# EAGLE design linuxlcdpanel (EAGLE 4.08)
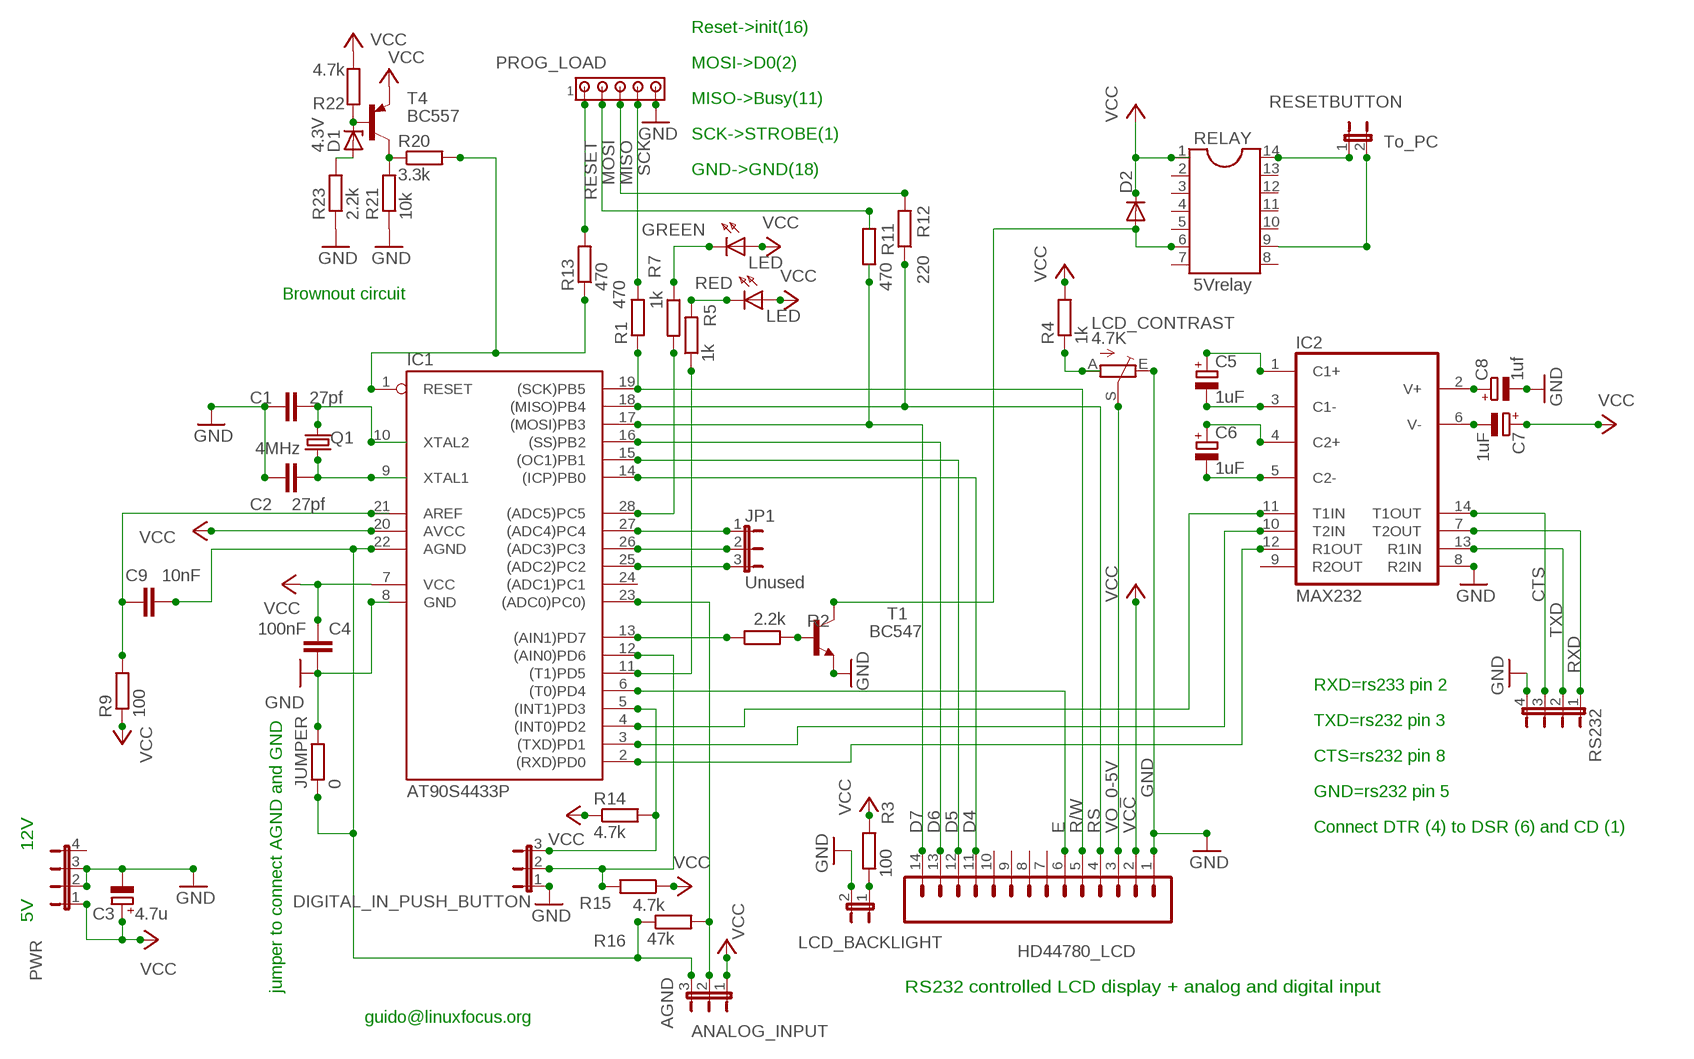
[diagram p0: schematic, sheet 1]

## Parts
ANALOG_INPUT  JP2E  [JP2]
C1  27pf  C2.5/2  [C2.5-2]
C2  27pf  C2.5/2  [C2.5-2]
C3  4.7u  CPOL-EUE2.5-7  [E2,5-7]
C4  100nF  C-EU025-040X050  [C025-040X050]
C5  1uF  CPOL-EUE2.5-6  [E2,5-6]
C6  1uF  CPOL-EUE2.5-6  [E2,5-6]
C7  1uF  CPOL-EUE2.5-7  [E2,5-7]
C8  1uf  CPOL-EUE2.5-6  [E2,5-6]
C9  10nF  C-EU025-030X050  [C025-030X050]
D1  4.3V  ZENER-DIODEZD-5  [ZDIO-5]
D2  DIODE-D-5  [D-5]
DIGITAL_IN_PUSH_BUTTON  JP2E  [JP2]
GREEN  LED  LED3MM  [LED3MM]
HD44780_LCD  M14  [14P]
IC1  AT90S4433P  [DIL28-3]
IC2  MAX232  [DIL16]
JP1  Unused  JP2E  [JP2]
JUMPER  0  R-EU_0204/7  [0204/7]
LCD_BACKLIGHT  JP1E  [JP1]
LCD_CONTRAST  4.7K  TRIM_EU-LI10  [LI10]
PROG_LOAD  MTA05-100  [10X05MTA]
PWR  JP4E  [JP4]
Q1  4MHz  HC49U-V  [HC49U-V]
R1  470  R-EU_0207/10  [0207/10]
R2  2.2k  R-EU_0204/7  [0204/7]
R3  100  R-EU_0207/10  [0207/10]
R4  1k  R-EU_0204/7  [0204/7]
R5  1k  R-EU_0204/7  [0204/7]
R7  1k  R-EU_0204/7  [0204/7]
R9  100  R-EU_0204/7  [0204/7]
R11  470  R-EU_0207/10  [0207/10]
R12  220  R-EU_0207/10  [0207/10]
R13  470  R-EU_0207/10  [0207/10]
R14  4.7k  R-EU_0207/10  [0207/10]
R15  4.7k  R-EU_0204/7  [0204/7]
R16  47k  R-EU_0204/7  [0204/7]
R20  3.3k  R-EU_0204/7  [0204/7]
R21  10k  R-EU_0204/7  [0204/7]
R22  4.7k  R-EU_0204/7  [0204/7]
R23  2.2k  R-EU_0204/7  [0204/7]
RED  LED  LED3MM  [LED3MM]
RELAY  5Vrelay  DIL14  [DIL14]
RESETBUTTON  To_PC  JP1E  [JP1]
RS232  JP4E  [JP4]
T1  BC547  [TO92]
T4  BC557  [TO92]

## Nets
26: IC1.26((ADC3)PC3) JP1.2
AGND: ANALOG_INPUT.3 C9.2 IC1.22(AGND) JUMPER.1 R16.1
AREF: C9.1 IC1.21(AREF) R9.2
CTS: IC2.14(T1OUT) RS232.3
D4: HD44780_LCD.11 IC1.14((ICP)PB0)
D5: HD44780_LCD.12 IC1.15((OC1)PB1)
D6: HD44780_LCD.13 IC1.16((SS)PB2)
D7: HD44780_LCD.14 IC1.17((MOSI)PB3) R11.1
E: HD44780_LCD.6 IC1.6((T0)PD4)
GND: C1.1 C2.1 C3.- C4.2 C8.- DIGITAL_IN_PUSH_BUTTON.1 HD44780_LCD.1 IC1.8(GND) IC2.8(R2IN) JUMPER.2 LCD_BACKLIGHT.2 LCD_CONTRAST.E PROG_LOAD.5 PWR.2 PWR.3 R21.1 R23.1 RS232.4 T1.1(E)
MISO: PROG_LOAD.3 R12.2
MOSI: PROG_LOAD.2 R11.2
N$2: C2.2 IC1.9(XTAL1) Q1.1
N$3: LCD_BACKLIGHT.1 R3.1
N$4: R2.2 T1.2(B)
N$5: IC1.28((ADC5)PC5) R7.2
N$6: DIGITAL_IN_PUSH_BUTTON.3 IC1.5((INT1)PD3) R14.2
N$7: GREEN.K(C) R7.1
N$8: RELAY.9 RESETBUTTON.2
N$9: RELAY.14 RESETBUTTON.1
N$13: IC1.11((T1)PD5) R5.1
N$14: IC1.13((AIN1)PD7) R2.1
N$17: R5.2 RED.K(C)
N$19: DIGITAL_IN_PUSH_BUTTON.2 IC1.12((AIN0)PD6) R15.2
N$24: IC1.1(RESET) R13.1 R20.2
N$25: C6.- IC2.5(C2-)
N$26: C6.+ IC2.4(C2+)
N$27: C7.- IC2.6(V-)
N$28: C8.+ IC2.2(V+)
N$29: C5.- IC2.3(C1-)
N$30: C5.+ IC2.1(C1+)
N$31: IC1.3((TXD)PD1) IC2.10(T2IN)
N$32: IC1.4((INT0)PD2) IC2.11(T1IN)
N$33: ANALOG_INPUT.2 IC1.23((ADC0)PC0)) R16.2
N$34: IC1.2((RXD)PD0) IC2.12(R1OUT)
N$36: C1.2 IC1.10(XTAL2) Q1.2
N$37: IC1.27((ADC4)PC4) JP1.1
N$39: IC1.25((ADC2)PC2) JP1.3
N$45: LCD_CONTRAST.A R4.1
N$46: R20.1 R21.2 T4.3(C)
N$47: D1.A R23.2
N$48: D1.C R22.1 T4.2(B)
R/W: HD44780_LCD.5 IC1.19((SCK)PB5) R1.1
RCTL: D2.A RELAY.6 T1.3(C)
RESET: PROG_LOAD.1 R13.2
RS: HD44780_LCD.4 IC1.18((MISO)PB4) R12.1
RXD: IC2.7(T2OUT) RS232.1
SCK: PROG_LOAD.4 R1.2
TXD: IC2.13(R1IN) RS232.2
VCC: ANALOG_INPUT.1 C3.+ C4.1 C7.+ D2.C GREEN.A HD44780_LCD.2 IC1.7(VCC) IC1.20(AVCC) PWR.1 R3.2 R4.2 R9.1 R14.1 R15.1 R22.2 RED.A RELAY.1 T4.1(E)
VO_0-5V: HD44780_LCD.3 LCD_CONTRAST.S
Unconnected: HD44780_LCD.7 HD44780_LCD.8 HD44780_LCD.9 HD44780_LCD.10 IC1.24((ADC1)PC1) IC2.9(R2OUT) PWR.4 RELAY.2 RELAY.3 RELAY.4 RELAY.5 RELAY.7 RELAY.8 RELAY.10 RELAY.11 RELAY.12 RELAY.13

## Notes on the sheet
- Reset->init(16)
- MOSI->D0(2)
- MISO->Busy(11)
- SCK->STROBE(1)
- GND->GND(18)
- Brownout circuit
- RXD=rs233 pin 2
- TXD=rs232 pin 3
- CTS=rs232 pin 8
- GND=rs232 pin 5
- Connect DTR (4) to DSR (6) and CD (1)
- 12V
- 5V
- jumper to connect AGND and GND | RS232 controlled LCD display + analog and digital input
- guido@linuxfocus.org

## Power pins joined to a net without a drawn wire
GND: IC2.15(GND)
VCC: IC2.16(VCC)

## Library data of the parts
ANALOG_INPUT DIGITAL_IN_PUSH_BUTTON JP1 = jumper:JP2E: JUMPER
C1 C2 = capacitor-wima:C: CAPACITOR
C3 C5-C8 = rcl:CPOL-EU: POLARIZED CAPACITOR, European symbol
C4 C9 = rcl:C-EU: CAPACITOR, European symbol
D1 = diode:ZENER-DIODE: Z-Diode
D2 = diode:DIODE-: DIODE
GREEN RED = led:LED3MM: LED
HD44780_LCD = con-amp-quick:M14: AMP QUICK CONNECTOR
IC1 = atmel:AT90S4433: MICROCONTROLLER 4 Kbytes FLASH 128 bytes SRAM 256 bytes EEPROM UART 6-channel 10 bit ADC
IC2 = maxim:MAX232: RS232 TRANSEIVER
JUMPER R1-R3 R5 R7 R9 R11-R14 R16 = rcl:R-EU_: RESISTOR, European symbol
LCD_BACKLIGHT RESETBUTTON = jumper:JP1E: JUMPER
LCD_CONTRAST = pot:TRIM_EU-: POTENTIOMETER
PROG_LOAD = con-amp:MTA05-100: AMP CONNECTOR
PWR RS232 = jumper:JP4E: JUMPER
Q1 = crystal:HC49U-V: CRYSTAL
R4 R15 R20-R23 = rcl_gus:R-EU_: RESISTOR, European symbol
RELAY = dil:DIL14: SOCKET Dual In Line
T1 = transistor-npn:BC547: NPN TRANSISTOR
T4 = transistor-pnp:BC557: PNP TRANSISTOR

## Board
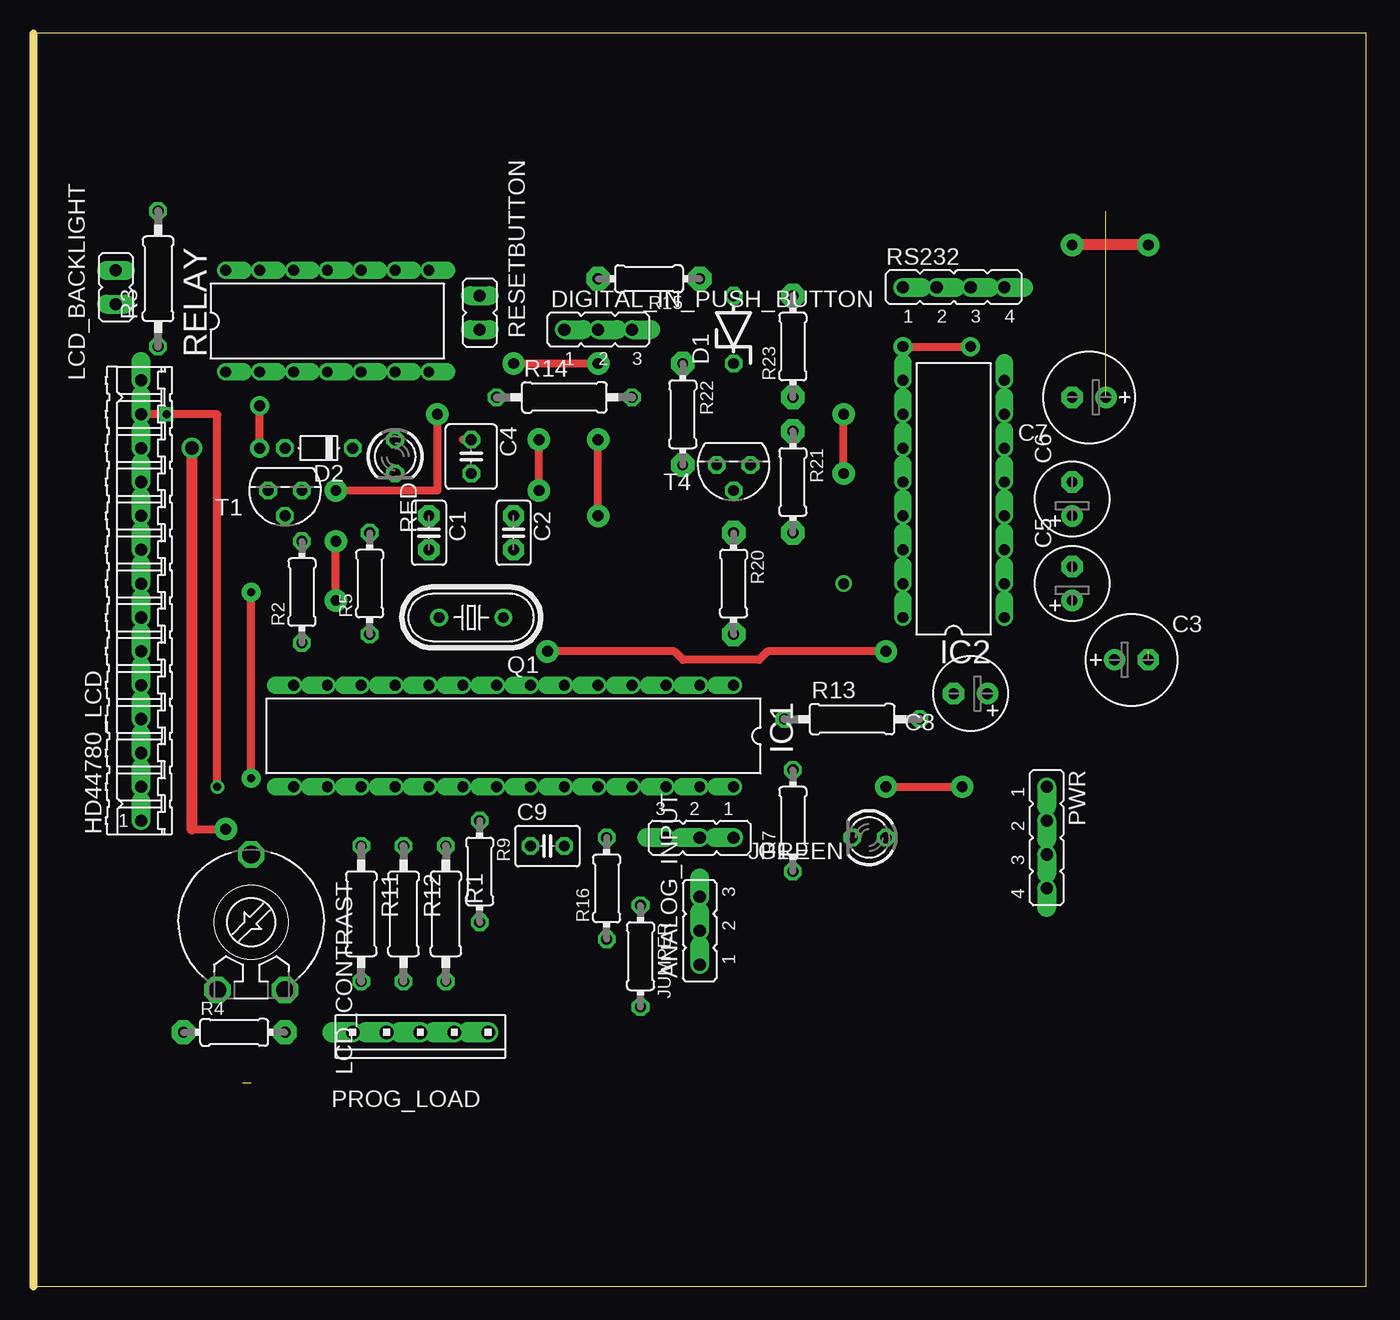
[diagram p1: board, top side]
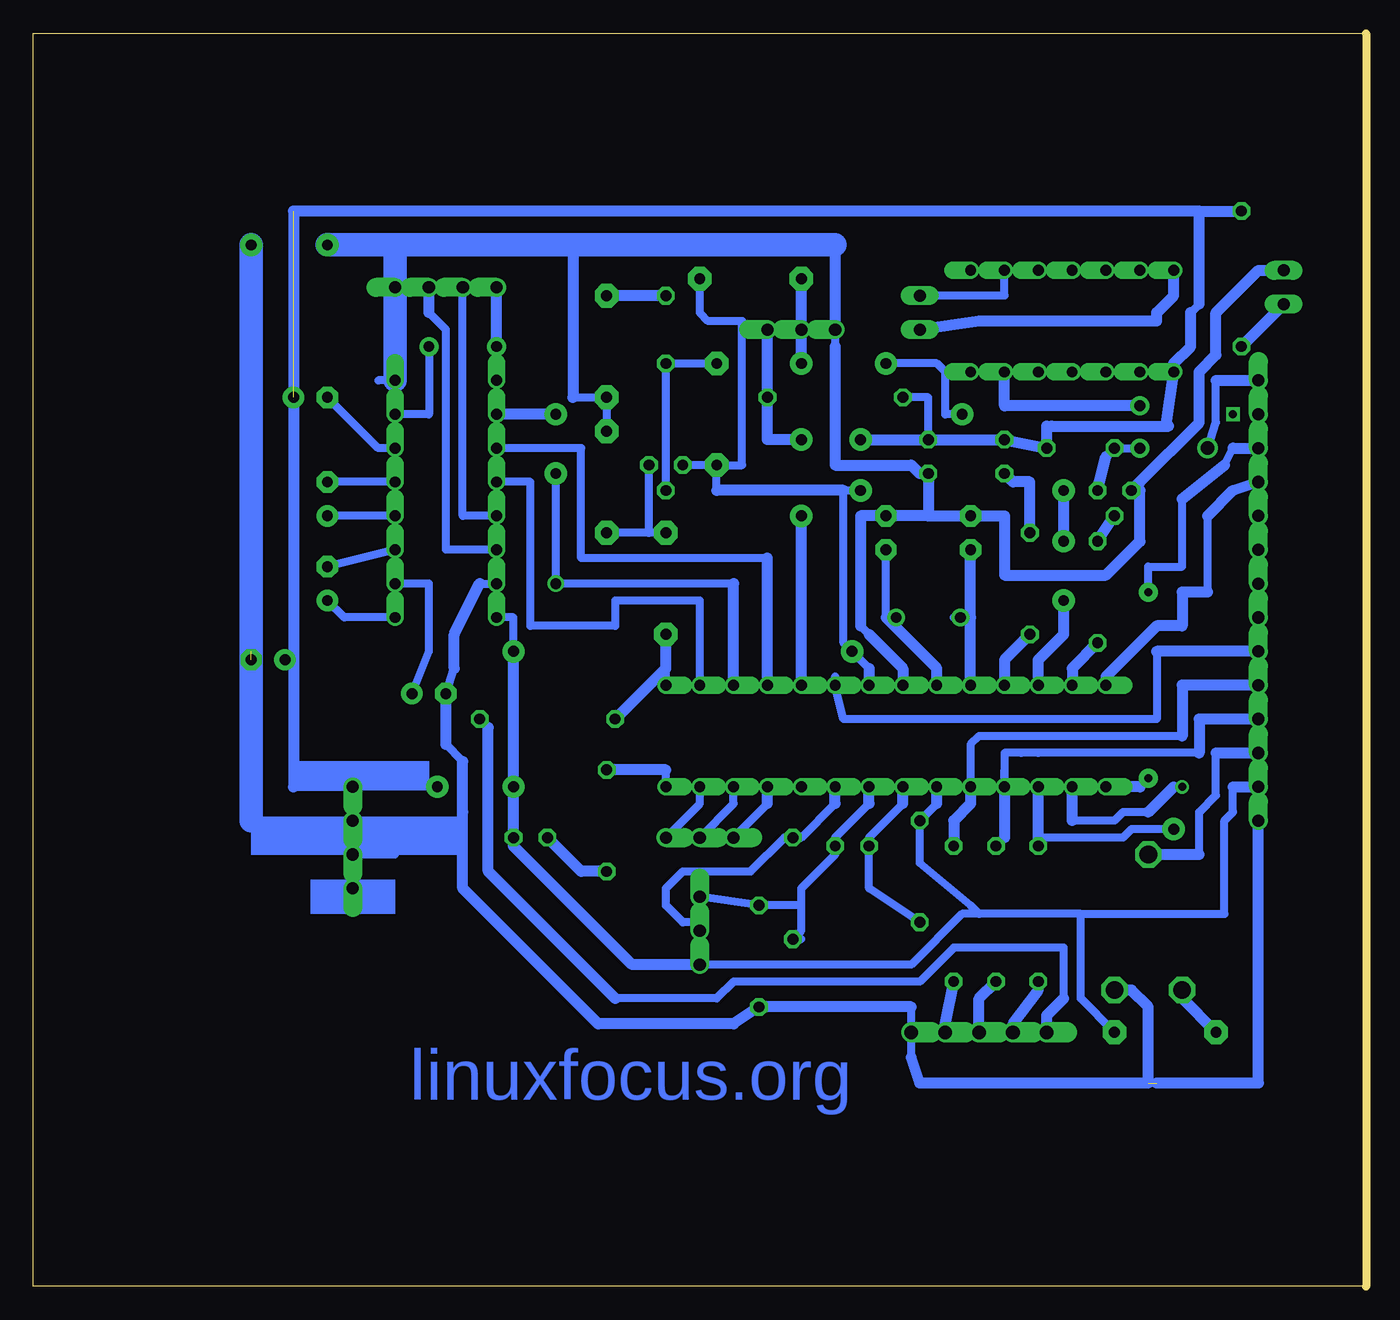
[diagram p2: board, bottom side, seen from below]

Size 100 x 93.97 mm. Coordinates in mm from the lower left corner, seen from the top.
Outline: 0,0 100,0 100,93.97 0,93.97 0,0
Copper layers used: Top, Bottom

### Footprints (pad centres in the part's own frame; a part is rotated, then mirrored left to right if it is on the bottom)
JP2 = drill 0.914 offset: 1 -2.54,0; 2 0,0; 3 2.54,0
C2.5-2 = drill 0.813 pad 1.6 octagon: 1 -1.27,0; 2 1.27,0
E2,5-7 = drill 0.813 pad 1.6 round: + -1.27,0 | drill 0.813 pad 1.6 octagon: - 1.27,0
C025-040X050 = drill 0.813 octagon: 1 -1.27,0; 2 1.27,0
E2,5-6 = drill 0.813 pad 1.6 round: + -1.27,0 | drill 0.813 pad 1.6 octagon: - 1.27,0
C025-030X050 = drill 0.813 octagon: 1 -1.27,0; 2 1.27,0
ZDIO-5 = drill 0.813 octagon: A 2.54,0; C -2.54,0
D-5 = drill 0.813 octagon: A 2.54,0; C -2.54,0
LED3MM = drill 0.813 octagon: A -1.27,0; K 1.27,0
14P = drill 0.914 offset: 1 -16.51,0; 2 -13.97,0; 3 -11.43,0; 4 -8.89,0; 5 -6.35,0; 6 -3.81,0; 7 -1.27,0; 8 1.27,0; 9 3.81,0; 10 6.35,0; 11 8.89,0; 12 11.43,0; 13 13.97,0; 14 16.51,0
DIL28-3 = drill 0.813 offset: 1 -16.51,-3.81; 2 -13.97,-3.81; 3 -11.43,-3.81; 4 -8.89,-3.81; 5 -6.35,-3.81; 6 -3.81,-3.81; 7 -1.27,-3.81; 8 1.27,-3.81; 9 3.81,-3.81; 10 6.35,-3.81; 11 8.89,-3.81; 12 11.43,-3.81; 13 13.97,-3.81; 14 16.51,-3.81; 15 16.51,3.81; 16 13.97,3.81; 17 11.43,3.81; 18 8.89,3.81; 19 6.35,3.81; 20 3.81,3.81; 21 1.27,3.81; 22 -1.27,3.81; 23 -3.81,3.81; 24 -6.35,3.81; 25 -8.89,3.81; 26 -11.43,3.81; 27 -13.97,3.81; 28 -16.51,3.81
DIL16 = drill 0.813 offset: 1 -8.89,-3.81; 2 -6.35,-3.81; 3 -3.81,-3.81; 4 -1.27,-3.81; 5 1.27,-3.81; 6 3.81,-3.81; 7 6.35,-3.81; 8 8.89,-3.81; 9 8.89,3.81; 10 6.35,3.81; 11 3.81,3.81; 12 1.27,3.81; 13 -1.27,3.81; 14 -3.81,3.81; 15 -6.35,3.81; 16 -8.89,3.81
0204/7 = drill 0.813 octagon: 1 -3.81,0; 2 3.81,0
JP1 = drill 0.914 long: 1 0,-1.27; 2 0,1.27
LI10 = drill 1.321 octagon: A -2.54,-5.08; E 2.54,-5.08; S 0,5.08
10X05MTA = drill 1.016 offset: 1 5.08,0; 2 2.54,0; 3 0,0; 4 -2.54,0; 5 -5.08,0
JP4 = drill 0.914 offset: 1 -3.81,0; 2 -1.27,0; 3 1.27,0; 4 3.81,0
HC49U-V = drill 0.813 round: 1 -2.413,0; 2 2.413,0
0207/10 = drill 0.813 octagon: 1 -5.08,0; 2 5.08,0
0204/7' = drill 0.813 pad 1.778 octagon: 1 -3.81,0; 2 3.81,0
DIL14 = drill 0.813 offset: 1 -7.62,-3.81; 2 -5.08,-3.81; 3 -2.54,-3.81; 4 0,-3.81; 5 2.54,-3.81; 6 5.08,-3.81; 7 7.62,-3.81; 8 7.62,3.81; 9 5.08,3.81; 10 2.54,3.81; 11 0,3.81; 12 -2.54,3.81; 13 -5.08,3.81; 14 -7.62,3.81
TO92 = drill 0.813 octagon: 1 1.27,0; 2 0,1.905; 3 -1.27,0

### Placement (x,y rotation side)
ANALOG_INPUT  50,26.66 90 top
C1  29.68,56.51 270 top
C2  36.03,56.51 270 top
C3  82.39,46.98 0 top
C4  32.85,62.22 270 top
C5  77.94,52.7 90 top
C6  77.94,59.05 90 top
C7  79.21,66.67 180 top
C8  70.32,44.45 180 top
C9  38.57,33.02 0 top
D1  52.54,71.75 90 top
D2  21.42,62.86 180 top
DIGITAL_IN_PUSH_BUTTON  42.38,71.75 0 top
GREEN  62.7,33.65 180 top
HD44780_LCD  8.09,51.43 90 top
IC1  36.03,41.27 180 top
IC2  69.05,59.05 90 top
JP1  50,33.65 180 top
JUMPER  45.55,24.76 270 top
LCD_BACKLIGHT  6.18,74.92 0 top
LCD_CONTRAST  16.34,27.3 0 top
PROG_LOAD  29.04,19.05 180 top
PWR  76.03,33.65 270 top
Q1  32.85,50.16 180 top
R1  30.95,27.93 270 top
R2  20.15,52.06 90 top
R3  9.36,75.56 90 top
R4  1k  [0204/7']  15.08,19.05 0 top
R5  25.23,52.7 90 top
R7  56.98,34.92 90 top
R9  33.49,31.11 270 top
R11  24.6,27.93 270 top
R12  27.77,27.93 270 top
R13  61.43,42.54 0 top
R14  39.84,66.67 0 top
R15  4.7k  [0204/7']  46.19,75.56 180 top
R16  43.02,29.84 90 top
R20  3.3k  [0204/7']  52.54,52.7 270 top
R21  10k  [0204/7']  56.98,60.32 270 top
R22  4.7k  [0204/7']  48.73,65.4 270 top
R23  2.2k  [0204/7']  56.98,70.48 90 top
RED  27.14,62.22 270 top
RELAY  22.06,72.39 0 top
RESETBUTTON  33.49,73.02 0 top
RS232  69.05,74.92 0 top
T1  18.88,59.69 180 top
T4  52.54,61.59 180 top

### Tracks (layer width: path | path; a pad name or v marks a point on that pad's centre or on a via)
26
  Bottom 0.61: JP1.2 47.46,36.19 IC1.26
AGND
  Bottom 0.61: 42.38,26.03 R16.1 42.38,26.66 42.38,28.57 | 37.3,36.19 39.84,33.65 C9.2 39.84,32.38 42.38,29.84 42.38,28.57 | 50,28.57 ANALOG_INPUT.3 JUMPER.1 42.38,28.57
  Bottom 0.813: 37.3,36.19 IC1.22
AREF
  Bottom 0.61: 34.76,36.19 37.3,33.65 C9.1 37.3,29.84 R9.2
  Bottom 0.813: 34.76,36.19 IC1.21
CTS
  Bottom 0.61: IC2.14 69.05,55.24 69.05,71.75 70.32,73.02
  Bottom 0.813: 70.32,73.02 RS232.3
D4
  Bottom 0.61: 19.52,45.72 IC1.14 | 11.9,52.06 11.9,57.78
  Bottom 0.813: 19.52,45.72 15.71,49.53 13.81,49.53 13.81,52.06 11.9,52.06 | 11.9,57.78 10,59.69 HD44780_LCD.11
D5  (via drill 0.61 pad 1.42)
  Top 0.61: v16.34,38.09 v16.34,52.06
  Bottom 0.61: v16.34,38.09 16.98,37.46 | v16.34,52.06 16.34,53.97 13.81,53.97 13.81,59.05 | 10.63,61.59 10,62.86
  Bottom 0.813: 16.98,37.46 IC1.15 | 13.81,59.05 10.63,61.59 | 10,62.86 HD44780_LCD.12
D6  (via drill 0.61)
  Top 0.61: v13.81,37.46 13.81,65.4 v10,65.4 HD44780_LCD.13
  Bottom 0.61: 22.06,34.92 18.88,34.92 18.25,35.55 16.34,35.55 | v13.81,37.46 14.44,37.46
  Bottom 0.813: 22.06,34.92 IC1.16 | 14.44,37.46 16.34,35.55
D7  (via drill 0.81 pad 1.68, 1.02)
  Top 0.61: 11.9,34.28 v14.44,34.28
  Top 0.813: 11.9,34.28 v11.9,62.86
  Bottom 0.61: R11.1 24.6,33.65 18.25,33.65 17.61,34.28 v14.44,34.28 | v11.9,62.86 11.27,64.77 11.27,67.94
  Bottom 0.813: 24.6,33.65 IC1.17 | 11.27,67.94 HD44780_LCD.14
E
  Bottom 0.61: IC1.6 39.84,45.72 | IC1.6 | IC1.6 39.2,42.54 15.71,42.54 15.71,47.62
  Bottom 0.813: HD44780_LCD.6 15.71,47.62
GND  (via drill 0.81 pad 1.68)  (2 unrouted)
  Top 0.813: v83.66,78.1 v77.94,78.1
  Bottom 0.254: 83.66,47.62 83.02,47.62
  Bottom 0.61: DIGITAL_IN_PUSH_BUTTON.1 39.84,70.48 | 39.84,70.48 | 28.41,57.78 29.04,57.78 C1.1 32.22,57.78 | 16.98,59.69 16.98,60.32 | 72.86,34.92 72.86,32.38 PWR.3 | C8.- 68.41,46.35 | R21.1 R23.1 59.52,66.67 | 72.86,34.92 67.78,34.92 67.78,35.55 | 67.78,39.36 69.05,40.64 | 72.86,34.92 PWR.2 83.66,34.92 | RS232.4 72.86,76.83 | 66.51,52.7 IC2.15 | IC2.8 74.13,67.94 | 33.49,60.95 C4.2 | 39.84,70.48 | 37.94,49.53 37.3,48.89 | 34.12,17.14 PROG_LOAD.5 34.12,20.95 | 9.36,15.24 16.34,15.24
  Bottom 0.813: 39.84,78.1 DIGITAL_IN_PUSH_BUTTON.1 | T1.1 16.98,60.32 12.54,64.77 12.54,68.58 11.27,69.84 11.27,73.02 8.09,76.2 LCD_BACKLIGHT.2 | 16.98,59.69 16.98,55.88 19.52,53.33 27.14,53.33 27.14,57.78 29.04,57.78 | 32.85,57.78 C1.1 | 32.85,57.78 C2.1 37.94,57.78 37.94,49.53 | 68.41,46.35 68.41,48.89 66.51,52.7 | 67.78,39.36 67.78,35.55 67.78,29.84 57.62,19.68 47.46,19.68 JUMPER.2 34.12,20.95 | 69.05,40.64 C8.- | 37.3,48.89 34.76,46.35 IC1.8 | C4.2 32.85,57.78 | 33.49,60.95 34.12,61.59 39.84,61.59 39.84,70.48 | 59.52,78.1 59.52,66.67 | 34.12,17.14 33.49,15.24 16.34,15.24 16.34,20.95 17.61,22.22 LCD_CONTRAST.E | HD44780_LCD.1 8.09,15.24 15.71,15.24
  Bottom 1.778: IC2.8 RS232.4 72.86,78.1 | 83.66,34.92 83.66,47.62 v83.66,78.1 | 39.84,78.1 59.52,78.1 72.86,78.1 | v77.94,78.1 72.86,78.1
MISO
  Bottom 0.813: R12.2 29.04,21.59 PROG_LOAD.3
MOSI
  Bottom 0.61: 24.6,22.22 R11.2 | PROG_LOAD.2 26.5,19.68
  Bottom 0.813: 26.5,19.68 24.6,22.22
N$2
  Bottom 0.61: C2.2 36.03,50.16 Q1.1
  Bottom 0.813: 36.03,50.16 32.22,46.35 IC1.9
N$3
  Bottom 0.813: R3.1 LCD_BACKLIGHT.1
N$4
  Bottom 0.813: R2.2 T1.2
N$5
  Bottom 0.61: IC1.28 52.54,38.73
  Bottom 0.813: 52.54,38.73 R7.2
N$6  (via drill 0.81 pad 1.68)
  Top 0.61: v42.38,57.78 v42.38,63.5
  Bottom 0.61: R14.2
  Bottom 0.813: DIGITAL_IN_PUSH_BUTTON.3 R14.2 44.92,63.5 v42.38,63.5 | IC1.5 v42.38,57.78
N$7
  Bottom 0.813: R7.1 58.89,31.11 GREEN.K
N$8
  Bottom 0.61: RELAY.9 27.14,74.29 RESETBUTTON.2
N$9
  Bottom 0.813: RELAY.14 14.44,74.29 15.71,73.02 15.71,72.39 29.04,72.39 RESETBUTTON.1
N$13
  Bottom 0.813: IC1.11 27.14,46.98 R5.1
N$14
  Bottom 0.813: R2.1 22.06,46.35 IC1.13
N$17
  Bottom 0.813: RED.K 26.5,60.32 25.23,60.32 R5.2
N$19  (via drill 0.81 pad 1.68)
  Top 0.61: v36.03,69.21 v42.38,69.21 | v30.31,65.4 30.31,59.69 v22.7,59.69 | v22.7,51.43 v22.7,55.88
  Bottom 0.61: 24.6,46.35 24.6,45.72 IC1.12 | v36.03,69.21 32.22,69.21 31.58,68.58 31.58,65.4 v30.31,65.4
  Bottom 0.813: R15.2 DIGITAL_IN_PUSH_BUTTON.2 v42.38,69.21 | v22.7,55.88 v22.7,59.69 | v22.7,51.43 22.7,48.89 24.6,46.98 24.6,45.72
N$24
  Bottom 0.61: IC1.1 52.54,46.35
  Bottom 0.813: R20.2 52.54,46.35 R13.1
N$25
  Bottom 0.61: IC2.5 C6.-
N$26
  Bottom 0.61: IC2.4 C6.+
N$27
  Bottom 0.61: IC2.6 74.13,62.86 C7.-
N$28
  Bottom 0.61: C8.+ 70.32,47.62 70.32,52.7 IC2.2
N$29
  Bottom 0.61: IC2.3 C5.-
N$30
  Bottom 0.61: IC2.1 76.67,50.16 C5.+
N$31  (via drill 0.81, 0.81 pad 1.68)
  Top 0.61: v60.8,60.95 v60.8,65.4
  Bottom 0.61: 47.46,52.7 v60.8,52.7 v60.8,60.95
  Bottom 0.813: v60.8,65.4 IC2.10 | IC1.3 47.46,52.7
N$32
  Bottom 0.61: IC1.4 44.92,45.72 | IC2.11 58.89,62.86 58.89,54.61 44.92,54.61
  Bottom 0.813: 44.92,45.72 44.92,54.61
N$33
  Bottom 0.61: 39.84,36.19 42.38,33.65 R16.2 43.65,33.65 46.19,31.11 51.27,31.11 52.54,29.84 52.54,28.57 51.27,27.3 50,27.3 ANALOG_INPUT.2
  Bottom 0.813: 39.84,36.19 IC1.23
N$34
  Bottom 0.61: IC2.12 62.7,60.32 62.7,49.53 56.35,49.53 56.35,51.43 50,51.43 IC1.2
N$36
  Bottom 0.61: 29.68,50.16 30.95,50.16 Q1.2
  Bottom 0.813: IC1.10 29.68,50.16 C1.2
N$37
  Bottom 0.61: JP1.1 50,36.19 IC1.27
N$39
  Bottom 0.61: JP1.3 44.92,36.19
  Bottom 0.813: 44.92,36.19 IC1.25
N$45
  Bottom 0.61: 13.81,21.59 LCD_CONTRAST.A
  Bottom 0.813: R4.1 13.81,21.59
N$46
  Bottom 0.61: R20.1 53.81,56.51 | 53.81,56.51 R21.2 | 53.81,56.51 T4.3
N$47
  Bottom 0.813: D1.A R23.2
N$48
  Bottom 0.61: R22.1 D1.C T4.2
R/W
  Bottom 0.61: IC1.19 29.68,40.64 29.04,41.27 13.81,41.27
  Bottom 0.813: R1.1 30.95,34.92 29.68,36.19 IC1.19 | 13.81,41.27 13.81,45.08 HD44780_LCD.5
RCTL  (via drill 0.81 pad 1.42)
  Top 0.61: v16.98,62.86 v16.98,66.03
  Bottom 0.61: v16.98,62.86 D2.A 19.52,62.22
  Bottom 0.813: RELAY.6 27.14,66.03 v16.98,66.03 | T1.3 19.52,62.22
RESET
  Bottom 0.61: 22.7,21.59 22.7,25.39 30.95,25.39 33.49,22.86 47.46,22.86 48.73,21.59 56.35,21.59 | 65.88,41.91 R13.2
  Bottom 0.813: PROG_LOAD.1 23.96,20.32 22.7,21.59 | 56.35,21.59 65.88,31.11 65.88,41.91
RS
  Bottom 0.61: 24.6,40 | 27.14,38.09 27.14,38.73 | 27.14,38.09 IC1.18 | 24.6,40 25.87,40 | 27.14,33.65 R12.1 | 24.6,40 27.14,40 | 27.14,40 | 27.14,40 27.14,38.09 | 12.54,40 24.6,40
  Bottom 0.813: IC1.18 27.14,33.65 | 12.54,40 12.54,42.54 HD44780_LCD.4
RXD  (via drill 0.81 pad 1.42)
  Top 0.61: v65.24,70.48 v70.32,70.48
  Bottom 0.61: v70.32,70.48 70.32,65.4 IC2.7
  Bottom 0.813: v65.24,70.48 RS232.1
SCK
  Bottom 0.61: PROG_LOAD.4 31.58,19.68
  Bottom 0.813: 31.58,19.68 R1.2
TXD
  Bottom 0.61: IC2.13 67.78,57.78 RS232.2
VCC  (via drill 0.81 pad 1.68)  (1 unrouted)
  Top 0.61: C4.1 32.22,63.5 | v37.94,59.69 v37.94,63.5 | v63.97,47.62 55.08,47.62 54.45,46.98 48.73,46.98 48.09,47.62 v38.57,47.62 | v63.97,37.46 v69.69,37.46
  Bottom 0.61: IC2.16 63.97,50.16 v63.97,47.62 v63.97,37.46 GREEN.A 63.97,33.02 | R22.2 T4.1 | C4.1 32.85,66.67 R14.1 | v37.94,59.69 39.2,59.69 39.2,48.25 v38.57,47.62 37.3,46.35 | 48.73,59.69 R22.2 | 32.22,36.19 R9.1 33.49,31.75 29.68,28.57 29.04,27.93 | v69.69,37.46 PWR.1 | 80.48,37.46 76.67,37.46 | R15.1 50,73.02 49.37,72.39 46.82,72.39 46.82,61.59 R22.2 | R4.2 21.42,21.59 21.42,27.93 | 21.42,27.93 29.04,27.93 | 29.04,27.93 30.31,27.93 34.12,24.12 ANALOG_INPUT.1 | 13.17,73.02 12.54,73.66 | RELAY.1 14.44,69.21 | 10,37.46 10,35.55 10.63,34.92 10.63,27.93 21.42,27.93 | 23.96,64.13 23.58,64.51
  Bottom 0.813: 12.54,80.64 R3.2 | 12.54,80.64 80.48,80.64 80.48,46.98 | RELAY.1 15.01,64.7 14.82,64.51 15.08,64.51 23.58,64.51 | 23.96,64.51 23.96,64.13 D2.C RED.A C4.1 v37.94,63.5 | 39.2,59.69 48.73,59.69 | 32.22,36.19 IC1.20 | 63.97,33.02 55.08,24.12 ANALOG_INPUT.1 | 37.3,46.35 IC1.7 | GREEN.A v63.97,37.46 v63.97,47.62 | 80.48,46.98 80.48,37.46 | 13.17,73.02 13.17,70.48 14.44,69.21 | 12.54,73.66 12.54,80.64 | 80.48,46.98 C3.+ | 10,37.46 HD44780_LCD.2
VO_0-5V
  Bottom 0.61: 11.27,40 11.27,36.83 12.54,35.55 12.54,32.38
  Bottom 0.813: 11.27,40 HD44780_LCD.3 | 12.54,32.38 LCD_CONTRAST.S
(copper drawn outside any net)
  shapes: Bottom area x4

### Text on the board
Bottom: linuxfocus.org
